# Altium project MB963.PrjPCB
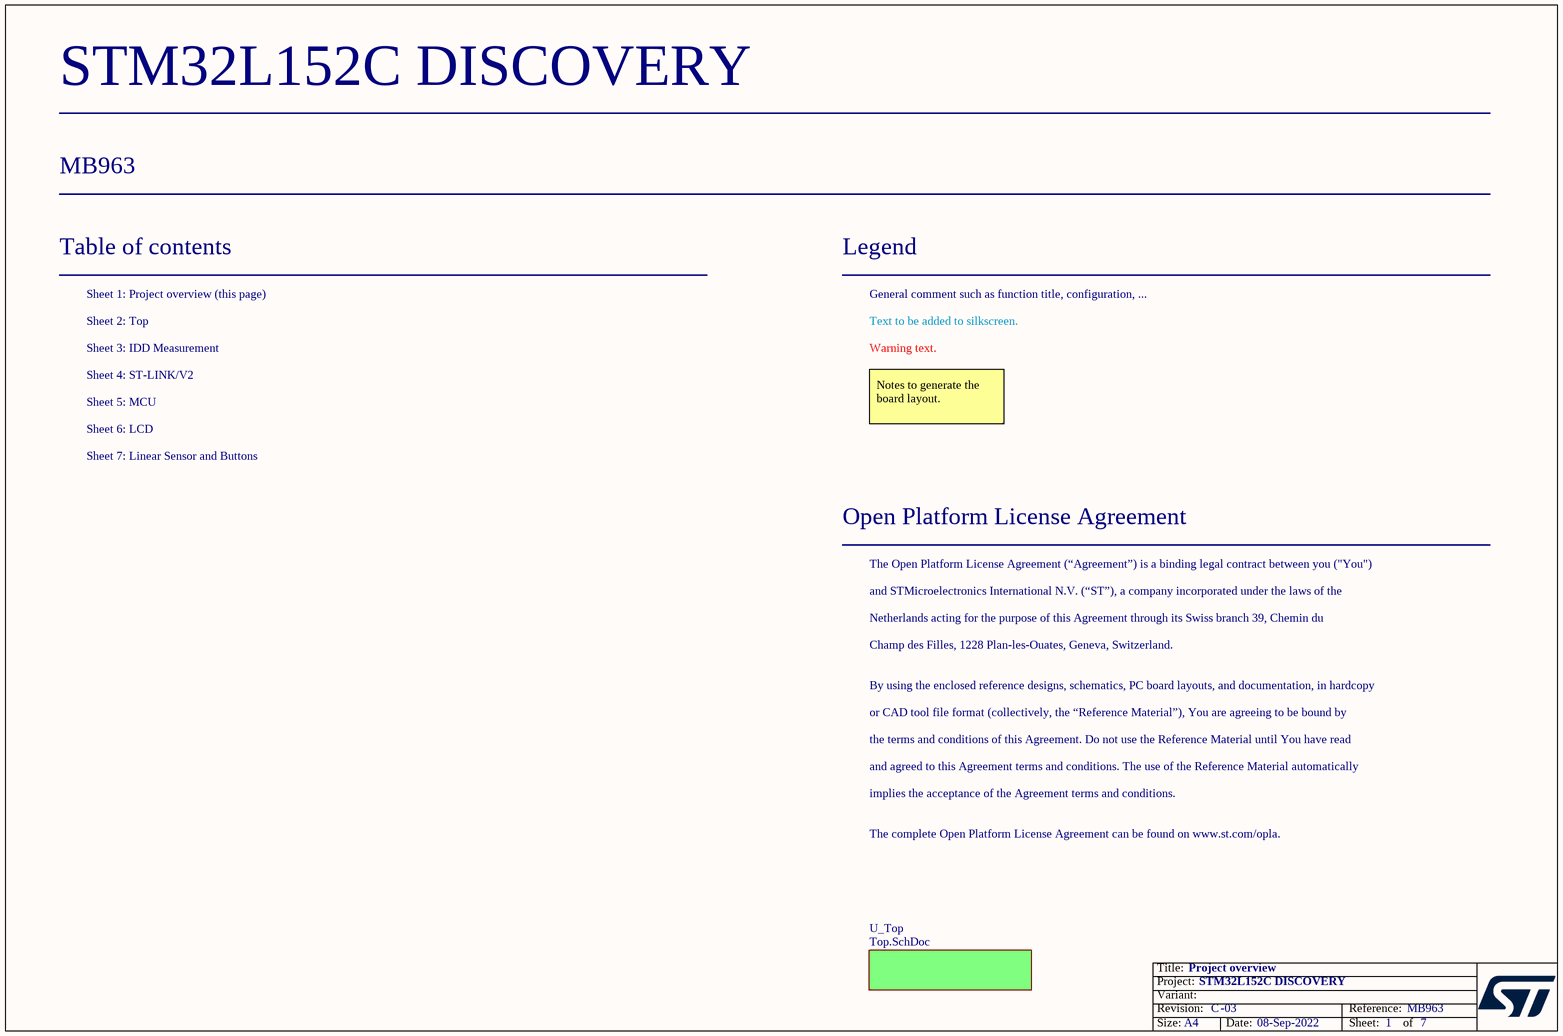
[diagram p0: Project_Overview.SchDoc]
Board_Assembly_Revision: 03; Board_Document_Date: 08-Sep-2022; Board_Name: STM32L152C DISCOVERY; Board_PCB_Revision: C; Board_Reference: MB963
7 sheets, 137 parts. Net scope: flat (ports and power ports of the same name join across sheets).
Board file: mb963b-meca-draw.PCBDOC
Sheets:
  Project_Overview.SchDoc
    U_Top = Top.SchDoc
      U_ST_LINK = ST_LINK.SCHDOC
      U_Power = IDD_measurement.SchDoc
      U_STM32L = STM32L.SchDoc
      U_SLIDER_PB = SLIDER_PB.SchDoc
      U_LCD_GH08172 = LCD_GH08172.SchDoc

## Sheet Project_Overview.SchDoc: Project overview
size A4; Date: Not used; ApprovedBy: Not used; CheckedBy: Not used; Author: Not used; CompanyName: STMicroelectronics; DrawnBy: Not used; Engineer: Not used; Organization: Not used; Address1: Not used; Address2: Not used; Address3: Not used; Address4: Not used; DocumentNumber: Not used; Revision: Not used; SheetNumber: 1; SheetTotal: 7

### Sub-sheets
U_Top = Top.SchDoc: no entries

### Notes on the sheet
- Table of contents
- Sheet 1: Project overview (this page)
- Legend
- General comment such as function title, configuration, ...
- Sheet 2: Top
- Sheet 3: IDD Measurement
- Sheet 4: ST-LINK/V2
- Text to be added to silkscreen.
- Warning text.
- Sheet 5: MCU
- Sheet 6: LCD
- Notes to generate the board layout.
- Sheet 7: Linear Sensor and Buttons
- Open Platform License Agreement
- The Open Platform License Agreement (“Agreement”) is a binding legal contract between you ("You")
- and STMicroelectronics International N.V. (“ST”), a company incorporated under the laws of the
- Netherlands acting for the purpose of this Agreement through its Swiss branch 39, Chemin du
- Champ des Filles, 1228 Plan-les-Ouates, Geneva, Switzerland.
- By using the enclosed reference designs, schematics, PC board layouts, and documentation, in hardcopy
- or CAD tool file format (collectively, the “Reference Material”), You are agreeing to be bound by
- the terms and conditions of this Agreement. Do not use the Reference Material until You have read
- and agreed to this Agreement terms and conditions. The use of the Reference Material automatically
- implies the acceptance of the Agreement terms and conditions.
- The complete Open Platform License Agreement can be found on www.st.com/opla.

## Sheet Top.SchDoc: Top
size A4; PageSetup: Record=PageOptions¦CenterHorizontal=True¦CenterVertical=True¦PrintScale=1.00¦XCorrection=1.00¦YCorrection=1.00¦PrintKind=1¦BorderSize=5000000¦LeftOffset=0¦BottomOffset=0¦Orientation=2¦PaperLength=1000¦PaperWidth=1000¦Scale=100¦PaperSource=15¦PrintQuality=1200¦MediaType=1¦DitherType=10¦PaperKind=A4¦PrintScaleMode=1; Date: Not used; ApprovedBy: Not used; CheckedBy: Not used; Author: Not used; CompanyName: STMicroelectronics; DrawnBy: Not used; Engineer: Not used; Organization: Not used; Address1: Not used; Address2: Not used; Address3: Not used; Address4: Not used; DocumentNumber: Not used; Revision: Not used; SheetNumber: 2; SheetTotal: 7
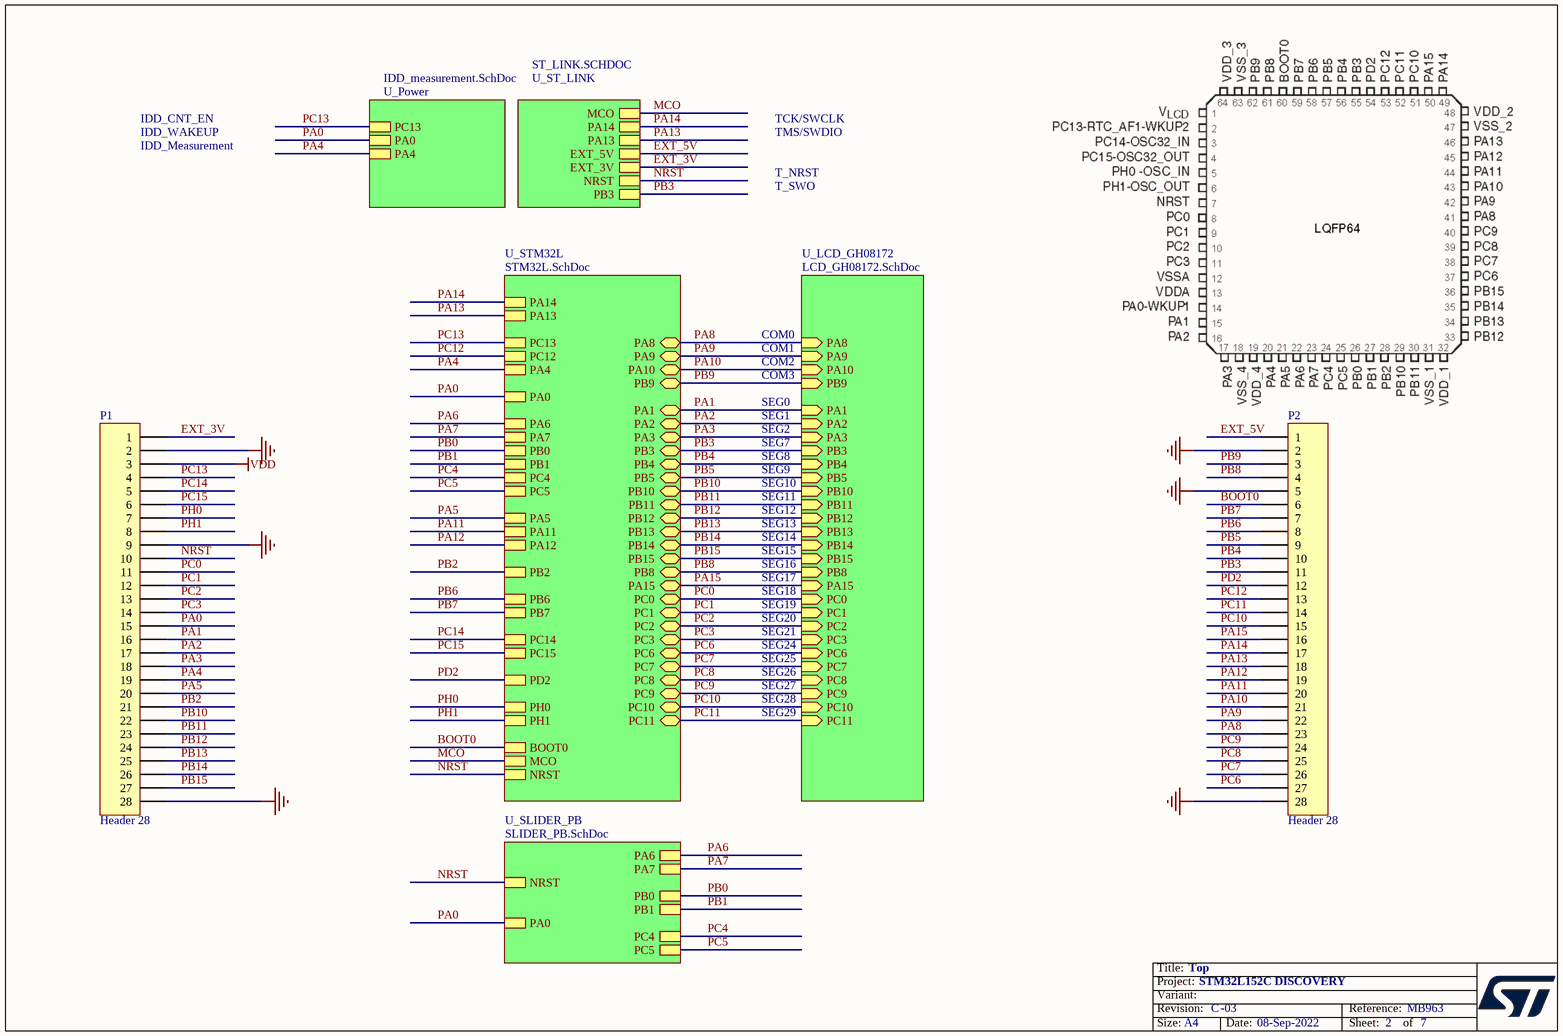
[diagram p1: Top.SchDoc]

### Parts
P1  Header 28  [HDR1X28]
P2  Header 28  [HDR1X28]

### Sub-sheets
U_LCD_GH08172 = LCD_GH08172.SchDoc: PB8 (in), PA15 (in), PB15 (in), PC2 (in), PC1 (in), PC0 (in), PC11 (in), PC10 (in), PC9 (in), PC8 (in), PC3 (in), PC7 (in), PC6 (in), PA8 (in), PA9 (in), PA10 (in), PA1 (in), PA2 (in), PA3 (in), PB3 (in), PB4 (in), PB5 (in), PB10 (in), PB11 (in), PB9 (in), PB12 (in), PB13 (in), PB14 (in)
U_Power = IDD_measurement.SchDoc: PA4, PA0, PC13
U_SLIDER_PB = SLIDER_PB.SchDoc: NRST, PA0, PB0, PC4, PA6, PA7, PC5, PB1
U_ST_LINK = ST_LINK.SCHDOC: PA13, PA14, EXT_5V, EXT_3V, MCO, NRST, PB3
U_STM32L = STM32L.SchDoc: PA13, PA14, PA15 (bidir), PA12, PA0, PA1 (bidir), PA2 (bidir), PA3 (bidir), PA4, PA5, PA6, PA7, PA8 (bidir), PA9 (bidir), PA10 (bidir), PA11, PB12 (bidir), PB0, PB1, PB2, PB3 (bidir), PB4 (bidir), PB5 (bidir), PB6, PB7, PB8 (bidir), PB9 (bidir), PB10 (bidir), PB11 (bidir), PB13 (bidir), PB14 (bidir), PB15 (bidir), PC3 (bidir), PC15, PC14, PC13, PC12, PC11 (bidir), PC10 (bidir), PC9 (bidir), PC8 (bidir), PC7 (bidir), PC6 (bidir), PC5, PC4, PC2 (bidir), PC1 (bidir), PC0 (bidir), PD2, BOOT0, PH1, PH0, NRST, MCO

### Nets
GND: P1.2 P1.9 P1.28 P2.2 P2.5 P2.28
VDD: P1.3
BOOT0: P2.6 ; sheet U_STM32L/BOOT0
EXT_3V: P1.1 ; sheet U_ST_LINK/EXT_3V
EXT_5V: P2.1 ; sheet U_ST_LINK/EXT_5V
MCO: sheet U_ST_LINK/MCO, sheet U_STM32L/MCO
NRST: P1.10 ; sheet U_ST_LINK/NRST, sheet U_STM32L/NRST, sheet U_SLIDER_PB/NRST
PA0: P1.15 ; sheet U_Power/PA0, sheet U_STM32L/PA0, sheet U_SLIDER_PB/PA0
PA1: P1.16 ; sheet U_STM32L/PA1, sheet U_LCD_GH08172/PA1
PA2: P1.17 ; sheet U_STM32L/PA2, sheet U_LCD_GH08172/PA2
PA3: P1.18 ; sheet U_STM32L/PA3, sheet U_LCD_GH08172/PA3
PA4: P1.19 ; sheet U_Power/PA4, sheet U_STM32L/PA4
PA5: P1.20 ; sheet U_STM32L/PA5
PA6: sheet U_STM32L/PA6, sheet U_SLIDER_PB/PA6
PA7: sheet U_STM32L/PA7, sheet U_SLIDER_PB/PA7
PA8: P2.23 ; sheet U_STM32L/PA8, sheet U_LCD_GH08172/PA8
PA9: P2.22 ; sheet U_STM32L/PA9, sheet U_LCD_GH08172/PA9
PA10: P2.21 ; sheet U_STM32L/PA10, sheet U_LCD_GH08172/PA10
PA11: P2.20 ; sheet U_STM32L/PA11
PA12: P2.19 ; sheet U_STM32L/PA12
PA13: P2.18 ; sheet U_ST_LINK/PA13, sheet U_STM32L/PA13
PA14: P2.17 ; sheet U_ST_LINK/PA14, sheet U_STM32L/PA14
PA15: P2.16 ; sheet U_STM32L/PA15, sheet U_LCD_GH08172/PA15
PB0: sheet U_STM32L/PB0, sheet U_SLIDER_PB/PB0
PB1: sheet U_STM32L/PB1, sheet U_SLIDER_PB/PB1
PB2: P1.21 ; sheet U_STM32L/PB2
PB3: P2.11 ; sheet U_ST_LINK/PB3, sheet U_STM32L/PB3, sheet U_LCD_GH08172/PB3
PB4: P2.10 ; sheet U_STM32L/PB4, sheet U_LCD_GH08172/PB4
PB5: P2.9 ; sheet U_STM32L/PB5, sheet U_LCD_GH08172/PB5
PB6: P2.8 ; sheet U_STM32L/PB6
PB7: P2.7 ; sheet U_STM32L/PB7
PB8: P2.4 ; sheet U_STM32L/PB8, sheet U_LCD_GH08172/PB8
PB9: P2.3 ; sheet U_STM32L/PB9, sheet U_LCD_GH08172/PB9
PB10: P1.22 ; sheet U_STM32L/PB10, sheet U_LCD_GH08172/PB10
PB11: P1.23 ; sheet U_STM32L/PB11, sheet U_LCD_GH08172/PB11
PB12: P1.24 ; sheet U_STM32L/PB12, sheet U_LCD_GH08172/PB12
PB13: P1.25 ; sheet U_STM32L/PB13, sheet U_LCD_GH08172/PB13
PB14: P1.26 ; sheet U_STM32L/PB14, sheet U_LCD_GH08172/PB14
PB15: P1.27 ; sheet U_STM32L/PB15, sheet U_LCD_GH08172/PB15
PC0: P1.11 ; sheet U_STM32L/PC0, sheet U_LCD_GH08172/PC0
PC1: P1.12 ; sheet U_STM32L/PC1, sheet U_LCD_GH08172/PC1
PC2: P1.13 ; sheet U_STM32L/PC2, sheet U_LCD_GH08172/PC2
PC3: P1.14 ; sheet U_STM32L/PC3, sheet U_LCD_GH08172/PC3
PC4: sheet U_STM32L/PC4, sheet U_SLIDER_PB/PC4
PC5: sheet U_STM32L/PC5, sheet U_SLIDER_PB/PC5
PC6: P2.27 ; sheet U_STM32L/PC6, sheet U_LCD_GH08172/PC6
PC7: P2.26 ; sheet U_STM32L/PC7, sheet U_LCD_GH08172/PC7
PC8: P2.25 ; sheet U_STM32L/PC8, sheet U_LCD_GH08172/PC8
PC9: P2.24 ; sheet U_STM32L/PC9, sheet U_LCD_GH08172/PC9
PC10: P2.15 ; sheet U_STM32L/PC10, sheet U_LCD_GH08172/PC10
PC11: P2.14 ; sheet U_STM32L/PC11, sheet U_LCD_GH08172/PC11
PC12: P2.13 ; sheet U_STM32L/PC12
PC13: P1.4 ; sheet U_Power/PC13, sheet U_STM32L/PC13
PC14: P1.5 ; sheet U_STM32L/PC14
PC15: P1.6 ; sheet U_STM32L/PC15
PD2: P2.12 ; sheet U_STM32L/PD2
PH0: P1.7 ; sheet U_STM32L/PH0
PH1: P1.8 ; sheet U_STM32L/PH1

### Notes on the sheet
- IDD_WAKEUP
- IDD_CNT_EN
- IDD_Measurement
- TCK/SWCLK
- TMS/SWDIO
- T_NRST
- T_SWO
- COM0
- COM1
- COM2
- COM3
- SEG0
- SEG1
- SEG2
- SEG7
- SEG8
- SEG9
- SEG10
- SEG11
- SEG12
- SEG13
- SEG14
- SEG15
- SEG16
- SEG17
- SEG18
- SEG19
- SEG20
- SEG21
- SEG24
- SEG25
- SEG26
- SEG27
- SEG28
- SEG29

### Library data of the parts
P1 P2 = Header 28: Header, 28-Pin

## Sheet ST_LINK.SCHDOC: ST-LINK/V2 (SWD only)
size A4; Date: Not used; ApprovedBy: Not used; CheckedBy: Not used; Author: Not used; CompanyName: STMicroelectronics; DrawnBy: Not used; Engineer: Not used; Organization: Not used; Address1: Not used; Address2: Not used; Address3: Not used; Address4: Not used; DocumentNumber: Not used; Revision: Not used; SheetNumber: 4; SheetTotal: 7
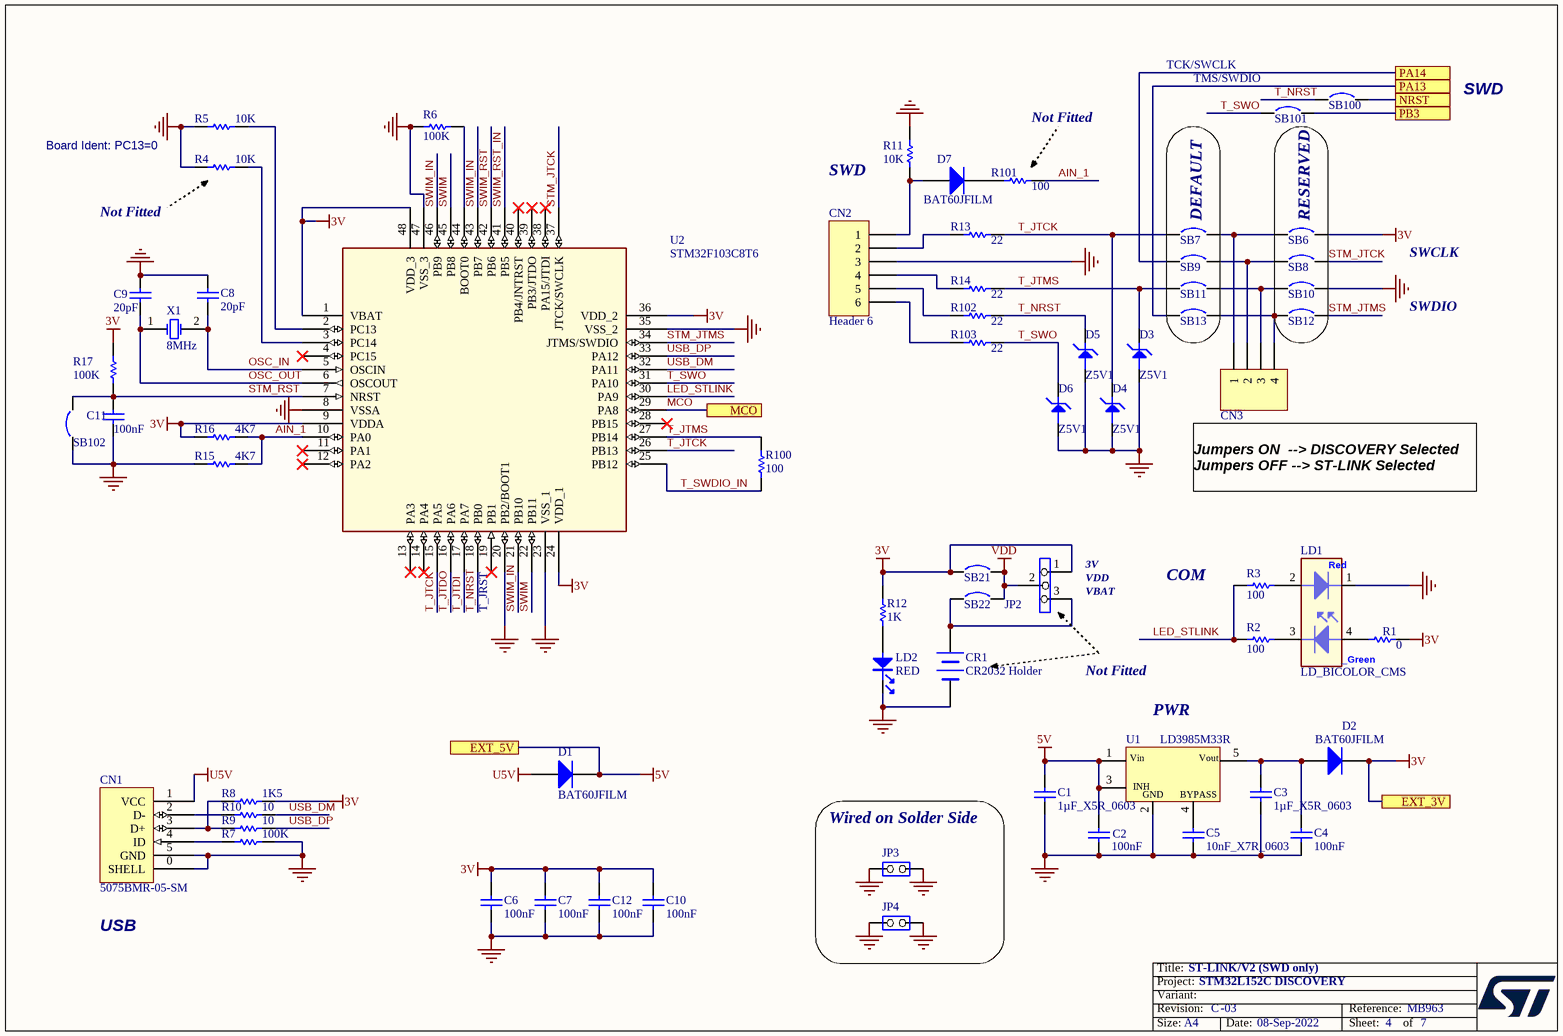
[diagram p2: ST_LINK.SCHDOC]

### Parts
C1  1µF_X5R_0603  [0603C]
C2  100nF  [0603C]
C3  1µF_X5R_0603  [0603C]
C4  100nF  [0603C]
C5  10nF_X7R_0603  [0603C]
C6  100nF  [0402C]
C7  100nF  [0402C]
C8  20pF  [0402C]
C9  20pF  [0402C]
C10  100nF  [0402C]
C11  100nF  [0402C]
C12  100nF  [0402C]
CN1  5075BMR-05-SM  [USB-MINI-B-SMD]
CN2  Header 6  [HDR1X6]
CN3  Header 4  [Header 4]  (value not drawn)
CR1  CR2032 Holder  [SOCKET BATTERY CR2032 (TRAV)]
D1  BAT60JFILM  [SOD323/A]
D2  BAT60JFILM  [SOD323/A]
D3  Z5V1  [SOT-23]
D4  Z5V1  [SOT-23]
D5  Z5V1  [SOT-23]
D6  Z5V1  [SOT-23]
D7  BAT60JFILM  [SOD323/A]
JP2  (no value)  [SIP3]
JP3  (no value)  [SIP2/2.54]
JP4  (no value)  [SIP2/2.54]
LD1  LD_BICOLOR_CMS  [HSMF-A201]
LD2  RED  [0603D]
R1  0  [0402R]
R2  100  [0402R]
R3  100  [0402R]
R4  10K  [0402R]
R5  10K  [0402R]
R6  100K  [0402R]
R7  100K  [0402R]
R8  1K5  [0402R]
R9  10  [0603R]
R10  10  [0603R]
R11  10K  [0402R]
R12  1K  [0402R]
R13  22  [0402R]
R14  22  [0402R]
R15  4K7  [0402R]
R16  4K7  [0402R]
R17  100K  [0402R]
R100  100  [0402R]
R101  100  [0402R]
R102  22  [0402R]
R103  22  [0402R]
SB6  Circuit Breaker  [JP2_SMD]  (value not drawn)
SB7  Circuit Breaker  [JP2_SMD]  (value not drawn)
SB8  Circuit Breaker  [JP2_SMD]  (value not drawn)
SB9  Circuit Breaker  [JP2_SMD]  (value not drawn)
SB10  Circuit Breaker  [JP2_SMD]  (value not drawn)
SB11  Circuit Breaker  [JP2_SMD]  (value not drawn)
SB12  Circuit Breaker  [JP2_SMD]  (value not drawn)
SB13  Circuit Breaker  [JP2_SMD]  (value not drawn)
SB21  Circuit Breaker  [JP2_SMD]  (value not drawn)
SB22  Circuit Breaker  [JP2_SMD]  (value not drawn)
SB100  Circuit Breaker  [JP2_SMD]  (value not drawn)
SB101  Circuit Breaker  [JP2_SMD]  (value not drawn)
SB102  Circuit Breaker  [JP2_SMD]  (value not drawn)
U1  LD3985M33R  [SOT-23-5L]
U2  STM32F103C8T6  [QFP48 7X7]
X1  8MHz  [XTAL1]

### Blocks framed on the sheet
DEFAULT: SB7 SB9 SB11 SB13
RESERVED: SB6 SB8 SB10 SB12
Wired on Solder Side: JP3 JP4

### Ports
EXT_3V, EXT_5V, MCO, NRST, PA13, PA14, PB3

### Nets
3V: C6.2 C7.2 C10.2 C12.1 D2.2(K) JP2.1 R1.2 R8.2 R12.2 R16.1 R17.2 SB6.2 SB21.1 U2.1(VBAT) U2.9(VDDA) U2.24(VDD_1) U2.36(VDD_2) U2.48(VDD_3) ; port EXT_3V
5V: C1.2 C2.2 D1.2(K) U1.1(Vin) U1.3(CE) ; port EXT_5V
GND: C1.1 C2.1 C3.2 C4.1 C5.1 C6.1 C7.1 C8.1 C9.1 C10.1 C11.1 C12.2 CN1.0(SHELL) CN1.5(GND) CN2.3 CR1.2(-) D3.2 D4.2 D5.2 D6.2 JP3.1(COMMON) JP3.2(NO) JP4.1(COMMON) JP4.2(NO) LD1.1 LD2.2 R4.1 R5.1 R6.1 R7.2 R11.2 R15.1 SB10.2 SB102.1 U1.2(GND) U2.8(VSSA) U2.20(PB2/BOOT1) U2.23(VSS_1) U2.35(VSS_2) U2.47(VSS_3)
U5V: CN1.1(VCC) D1.1(A)
VDD: JP2.2 SB21.2 SB22.2
AIN_1: R15.2 R16.2 R101.2 U2.10(PA0)
LED_STLINK: R2.1 R3.1 U2.30(PA9)
MCO: U2.29(PA8) ; port MCO
NRST: SB100.2 ; port NRST
OSC_IN: C8.2 U2.5(OSCIN) X1.2(OSC2)
OSC_OUT: C9.2 U2.6(OSCOUT) X1.1(OSC1)
PA13: SB13.1 ; port PA13
PA14: SB9.1 ; port PA14
PB3: SB101.2 ; port PB3
STM_JTCK: SB8.2 U2.37(JTCK/SWCLK)
STM_JTMS: SB12.2 U2.34(JTMS/SWDIO)
STM_RST: C11.2 R17.1 SB102.2 U2.7(NRST)
SWIM: U2.22(PB11) U2.45(PB8)
SWIM_IN: U2.21(PB10) U2.43(PB7) U2.46(PB9)
SWIM_RST: U2.42(PB6)
SWIM_RST_IN: U2.41(PB5)
T_JTCK: D4.3 R13.2 SB7.1 U2.15(PA5) U2.26(PB13)
T_JTDI: U2.17(PA7)
T_JTDO: U2.16(PA6)
T_JTMS: D3.3 R14.2 R100.2 SB11.1 U2.27(PB14)
T_NRST: D5.3 R102.2 SB100.1 U2.18(PB0)
T_SWDIO_IN: R100.1 U2.25(PB12)
T_SWO: D6.3 R103.2 SB101.1 U2.31(PA10)
USB_DM: R10.2 U2.32(PA11)
USB_DP: R9.2 U2.33(PA12)
NetC3_1: C3.1 C4.2 D2.1(A) U1.5(Vout)
NetC5_2: C5.2 U1.4(BYPASS)
NetCN1_2: CN1.2(D-) R10.1
NetCN1_3: CN1.3(D+) R8.1 R9.1
NetCN1_4: CN1.4(ID) R7.1
NetCN2_1: CN2.1 D7.1(A) R11.1
NetCN2_2: CN2.2 R13.1
NetCN2_4: CN2.4 R14.1
NetCN2_5: CN2.5 R102.1
NetCN2_6: CN2.6 R103.1
NetCN3_1: CN3.1 SB6.1 SB7.2
NetCN3_2: CN3.2 SB8.1 SB9.2
NetCN3_3: CN3.3 SB10.1 SB11.2
NetCN3_4: CN3.4 SB12.1 SB13.2
NetCR1_1: CR1.1(+) JP2.3 SB22.1
NetD7_2: D7.2(K) R101.1
NetLD1_2: LD1.2 R3.2
NetLD1_3: LD1.3 R2.2
NetLD1_4: LD1.4 R1.1
NetLD2_1: LD2.1 R12.1
NetR4_2: R4.2 U2.3(PC14)
NetR5_2: R5.2 U2.2(PC13)
NetR6_2: R6.2 U2.44(BOOT0)

Not connected (* = marked no-connect by the designer): U2 4(PC15)* 11(PA1)* 12(PA2)* 13(PA3)* 14(PA4)* 19(PB1)* 28(PB15)* 38(PA15/JTDI)* 39(PB3/JTDO)* 40(PB4/JNTRST)*

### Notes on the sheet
- TCK/SWCLK
- (near SB101) TMS/SWDIO
- SWD
- Board Ident: PC13=0
- Not Fitted
- SWCLK
- SWDIO
- Jumpers ON  --> DISCOVERY Selected
  Jumpers OFF --> ST-LINK Selected
- (near JP2) 3V
- (near JP2) VDD
- COM
- (near U2) T_JRST
- (near JP2) VBAT
- (near U1) PWR
- USB

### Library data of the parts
C1 C3 = CAP SMD 0603  X5R 1µF 25V 10%: 0603  X5R 1µF; Rated voltage: 25V; Tolerance: 10%
C2 C4 C6-C12 = Cap: Capacitor
C5 = CAP SMD 0603  X7R 10000PF 50V 10%: 0603  X7R 10NF; Order code RS: 2040779; Rated voltage: 50V; Tolerance: 10%
CN1 = USB-MINI-typeB connector
CN2 = Header 6: Header, 6-Pin
CN3 = Header 4: Header, 4-Pin
CR1 = BATTERY: Battery CR2032 with SOCKET; Manuf_1: Lotes; Manuf_Part_1: KB7410AP2L; Fitted: NO
D1 D2 D7 = Diode: Default Diode; Code - JEDEC: DO-214-AB; Provided: ST
D3-D6 = Z5V6: BZX84-C5V6; Fitted: NO
JP2 = Jumper3: Fitted: NO
JP3 JP4 = JP2
LD1 = LD_BICOLOR_CMS: Bicolor Led; Manuf_Part_1: HSMF-A201-A00J1; Manuf_1: Avago Technologies; Ref St: xxxxxx; cap_dec: ----
LD2 = PHOTO
R1-R3 R5-R17 R100 R102 R103 = res1: Resistor
R4 R101 = res1: Resistor; Fitted: NO
SB6 SB8 SB10 SB12 SB21 SB100 SB101 = Circuit Breaker: Solder: YES
SB7 SB9 SB11 SB13 SB22 SB102 = Circuit Breaker: Solder: NO
U1 = LD3985: Manuf_1: STM; Provided: ST
U2 = STM32F103C8T6: Manuf_1: STM; Ref St: 9175981; Provided: ST
X1 = XTAL: Crystal Oscillator

## Sheet IDD_measurement.SchDoc: IDD Measurement
size A4; Date: Not used; ApprovedBy: Not used; CheckedBy: Not used; Author: Not used; CompanyName: STMicroelectronics; DrawnBy: Not used; Engineer: Not used; Organization: Not used; Address1: Not used; Address2: Not used; Address3: Not used; Address4: Not used; DocumentNumber: Not used; Revision: Not used; SheetNumber: 3; SheetTotal: 7
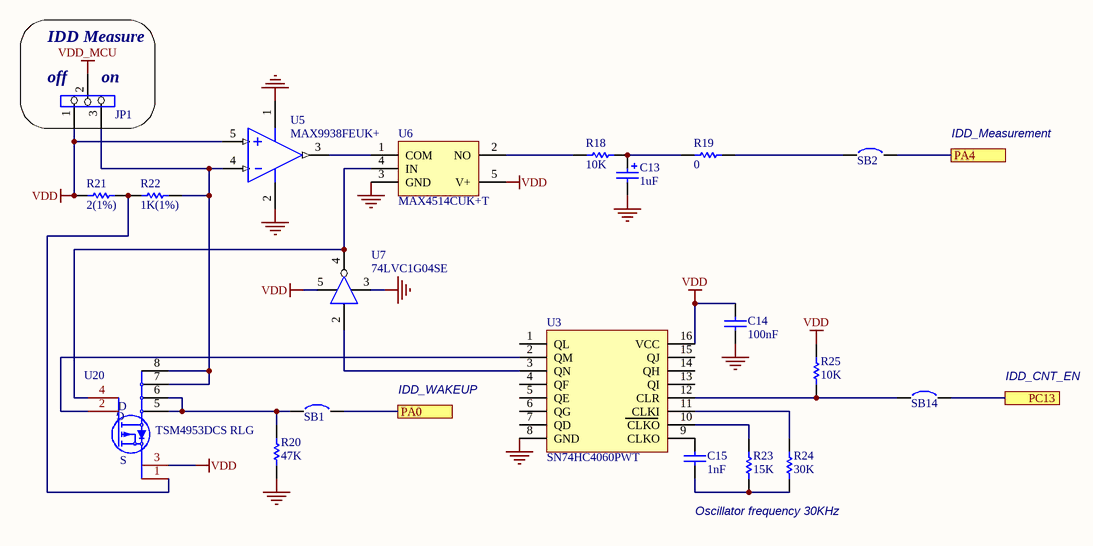
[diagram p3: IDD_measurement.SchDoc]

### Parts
C13  1uF  [0603C]
C14  100nF  [0402C]
C15  1nF  [0402C]
JP1  (no value)  [SIP3]
R18  10K  [0402R]
R19  0  [0402R]
R20  47K  [0402R]
R21  2(1%)  [0402R]
R22  1K(1%)  [0402R]
R23  15K  [0402R]
R24  30K  [0402R]
R25  10K  [0402R]
SB1  Circuit Breaker  [JP2_SMD]  (value not drawn)
SB2  Circuit Breaker  [JP2_SMD]  (value not drawn)
SB14  Circuit Breaker  [JP2_SMD]  (value not drawn)
U3  value SN74HC4060PWT  [ICC_TSSOP16_5P1X4P5_P065]  (hidden comment: SN74HC4060PWx)
U5  MAX9938FEUK+  [SOT-23-5L]
U6  value MAX4514CUK+T  [ICC_SOT23-5L_H1P45]  (hidden comment: MAX4514)
U7  74LVC1G04SE  [DIO_SOT353]
U20  value TSM4953DCS RLG  [ICC_SO8_5X4_P127]  (hidden comment: TSM4953DCS_RLG)

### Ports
PA0, PA4, PC13

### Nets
GND: C13.2 C14.1 R20.2 U3.8(GND) U5.1(GND) U5.2(GND) U6.3(GND) U7.3(GND)
VDD: C14.2 JP1.1 R21.2 R25.1 U3.16(VCC) U5.5(Vp) U6.5(V+) U7.5(VCC) U20.3(S)
VDD_MCU: JP1.2
PA0: SB1.2 ; port PA0
PA4: SB2.2 ; port PA4
PC13: SB14.2 ; port PC13
NetC13_1: C13.1 R18.2 R19.1
NetC15_1: C15.1 U3.9(CLKO)
NetC15_2: C15.2 R23.2 R24.2
NetJP1_3: JP1.3 R22.1 U5.4(Vm) U20.7(D) U20.8(D)
NetR18_1: R18.1 U6.2(NO)
NetR19_2: R19.2 SB2.1
NetR20_1: R20.1 SB1.1 U20.5(D) U20.6(D)
NetR21_1: R21.1 R22.2 U20.1(S)
NetR23_1: R23.1 U3.10(CLKO)
NetR24_1: R24.1 U3.11(CLKI)
NetR25_2: R25.2 SB14.1 U3.12(CLR)
NetU3_2: U3.2(QM) U20.2(S)
NetU3_3: U3.3(QN) U7.2(A)
NetU5_3: U5.3(OUT) U6.1(COM)
NetU6_4: U6.4(IN) U7.4(Y) U20.4(G)

Not connected (* = marked no-connect by the designer): U3 1(QL) 4(QF) 5(QE) 6(QG) 7(QD) 13(QI) 14(QH) 15(QJ); U7 1(NC)

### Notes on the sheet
- (near JP1) IDD Measure
- (near JP1) off
- (near JP1) on
- IDD_Measurement
- IDD_WAKEUP
- IDD_CNT_EN
- Oscillator frequency 30KHz

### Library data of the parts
C13 = Cap Pol1: Polarized Capacitor (Radial)
C14 C15 = Cap: Capacitor
JP1 = Jumper3
R18-R20 R22-R25 = res1: Resistor
R21 = res1: Resistor; Value: 2
SB1 SB2 SB14 = Circuit Breaker: Solder: YES
U3 = MCD-02070: 14-stage asynchronous  binary counter/oscillator; Part_Type: IC; Part_Preference: Recommended; Manufacturer: TEXAS INSTRUMENTS; Component_Country_Of_Origin: Malaysia; ShowFields: YES; ID: 4170
U5 = MAX9938: Precision Current-Sense Amplifier
U6 = MCD-02073: CMOS Analog Switches, Low-Voltage, Low-On-Resistance; Part_Type: IC; Part_Preference: Recommended; Manufacturer: MAXIM INTEGRATED; Order_Code_RS: 191-3316; Component_Country_Of_Origin: Thailand, Malaysia; ShowFields: YES; ID: 4173
U7 = MCD-00126: single Inverter Gate with a standard push-pull output. (1.65V to 5.5V); Part_Type: IC; Part_Preference: Recommended; Manufacturer: DIODES INCORPORATED; Component_Country_Of_Origin: Unknown; ShowFields: YES; ID: 2738
U20 = MCD-03226: Transistor, MOSFET, Dual P-Ch, 30V, -4.9A, SOP-8; Part_Preference: Recommended; Manufacturer: TAIWAN SEMICONDUCTOR; ShowFields: YES; ID: 5342

## Sheet STM32L.SchDoc: MCU
size A4; Date: Not used; ApprovedBy: Not used; CheckedBy: Not used; Author: Not used; CompanyName: STMicroelectronics; DrawnBy: Not used; Engineer: Not used; Organization: Not used; Address1: Not used; Address2: Not used; Address3: Not used; Address4: Not used; DocumentNumber: Not used; Revision: Not used; SheetNumber: 5; SheetTotal: 7
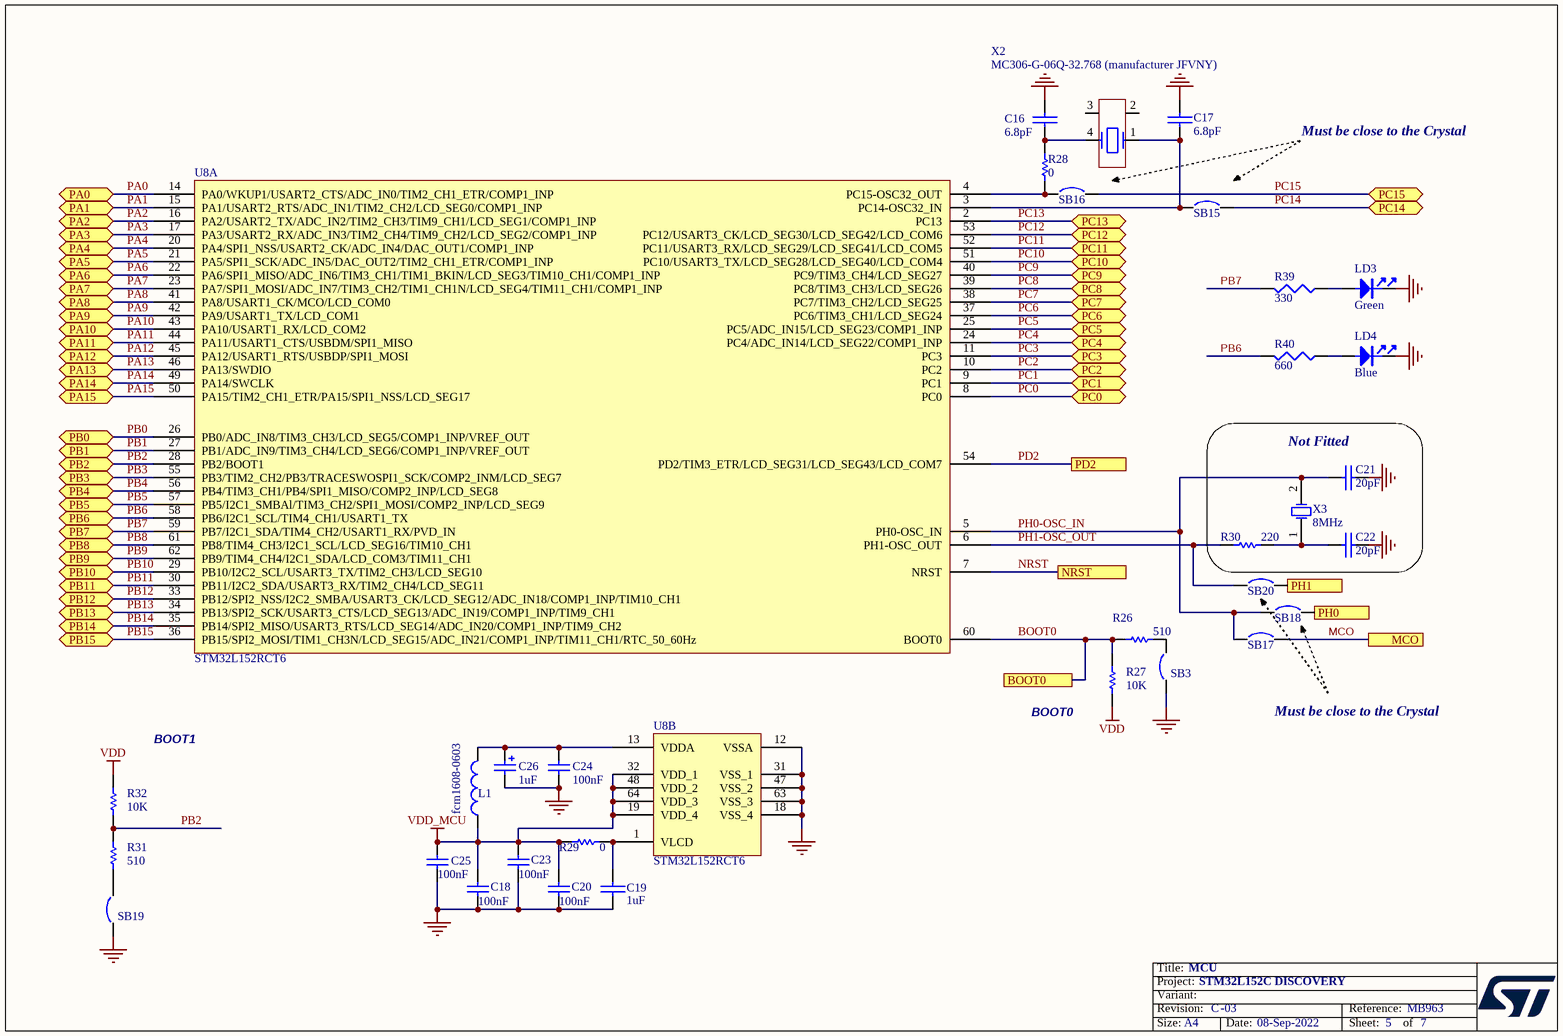
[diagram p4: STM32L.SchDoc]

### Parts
C16  6.8pF  [0603C]
C17  6.8pF  [0603C]
C18  100nF  [0402C]
C19  1uF  [0603C]
C20  100nF  [0402C]
C21  20pF  [0603C]
C22  20pF  [0603C]
C23  100nF  [0402C]
C24  100nF  [0402C]
C25  100nF  [0402C]
C26  1uF  [CASE-AA]
L1  fcm1608-0603  [0603L]
LD3  Green  [0603D]
LD4  Blue  [0603D]
R26  510  [0603R]
R27  10K  [0402R]
R28  0  [0603R]
R29  0  [0402R]
R30  220  [0603R]
R31  510  [0603R]
R32  10K  [0402R]
R39  330  [0603R]
R40  660  [0603R]
SB3  Circuit Breaker  [JP2_SMD]  (value not drawn)
SB15  Circuit Breaker  [JP2_SMD]  (value not drawn)
SB16  Circuit Breaker  [JP2_SMD]  (value not drawn)
SB17  Circuit Breaker  [JP2_SMD]  (value not drawn)
SB18  Circuit Breaker  [JP2_SMD]  (value not drawn)
SB19  Circuit Breaker  [JP2_SMD]  (value not drawn)
SB20  Circuit Breaker  [JP2_SMD]  (value not drawn)
U8  STM32L152RCT6  [QFP64]  (parts A,B of 2)
X2  MC306-G-06Q-32.768 (manufacturer JFVNY)  [MC306-CRYSTAL]
X3  8MHz  [XTAL1]

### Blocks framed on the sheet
Not Fitted: C21 C22 R30 X3

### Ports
BOOT0, MCO, NRST, PA0 (bidir), PA1 (bidir), PA2 (bidir), PA3 (bidir), PA4 (bidir), PA5 (bidir), PA6 (bidir), PA7 (bidir), PA8 (bidir), PA9 (bidir), PA10 (bidir), PA11 (bidir), PA12 (bidir), PA13 (bidir), PA14 (bidir), PA15 (bidir), PB0 (bidir), PB1 (bidir), PB2 (bidir), PB3 (bidir), PB4 (bidir), PB5 (bidir), PB6 (bidir), PB7 (bidir), PB8 (bidir), PB9 (bidir), PB10 (bidir), PB11 (bidir), PB12 (bidir), PB13 (bidir), PB14 (bidir), PB15 (bidir), PC0 (bidir), PC1 (bidir), PC2 (bidir), PC3 (bidir), PC4 (bidir), PC5 (bidir), PC6 (bidir), PC7 (bidir), PC8 (bidir), PC9 (bidir), PC10 (bidir), PC11 (bidir), PC12 (bidir), PC13 (bidir), PC14 (bidir), PC15 (bidir), PD2, PH0, PH1

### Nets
GND: C16.2 C17.2 C18.1 C19.2 C20.1 C21.1 C22.1 C23.2 C24.1 C25.1 C26.2 LD3.2 LD4.2 SB3.1 SB19.1 U8.12(VSSA) U8.18(VSS_4) U8.31(VSS_1) U8.47(VSS_2) U8.63(VSS_3)
VDD: R27.2 R32.1
VDD_MCU: C18.2 C20.2 C23.1 C25.2 L1.1 R29.1 U8.19(VDD_4) U8.32(VDD_1) U8.48(VDD_2) U8.64(VDD_3)
BOOT0: R26.2 R27.1 U8.60(BOOT0) ; port BOOT0
MCO: SB17.2 ; port MCO
NRST: U8.7(NRST) ; port NRST
PA0: U8.14(PA0/WKUP1/USART2_CTS/ADC_IN0/TIM2_CH1_ETR/COMP1_INP) ; port PA0
PA1: U8.15(PA1/USART2_RTS/ADC_IN1/TIM2_CH2/LCD_SEG0/COMP1_INP) ; port PA1
PA2: U8.16(PA2/USART2_TX/ADC_IN2/TIM2_CH3/TIM9_CH1/LCD_SEG1/COMP1_INP) ; port PA2
PA3: U8.17(PA3/USART2_RX/ADC_IN3/TIM2_CH4/TIM9_CH2/LCD_SEG2/COMP1_INP) ; port PA3
PA4: U8.20(PA4/SPI1_NSS/USART2_CK/ADC_IN4/DAC_OUT1/COMP1_INP) ; port PA4
PA5: U8.21(PA5/SPI1_SCK/ADC_IN5/DAC_OUT2/TIM2_CH1_ETR/COMP1_INP) ; port PA5
PA6: U8.22(PA6/SPI1_MISO/ADC_IN6/TIM3_CH1/TIM1_BKIN/LCD_SEG3/TIM10_CH1/COMP1_INP) ; port PA6
PA7: U8.23(PA7/SPI1_MOSI/ADC_IN7/TIM3_CH2/TIM1_CH1N/LCD_SEG4/TIM11_CH1/COMP1_INP) ; port PA7
PA8: U8.41(PA8/USART1_CK/MCO/LCD_COM0) ; port PA8
PA9: U8.42(PA9/USART1_TX/LCD_COM1) ; port PA9
PA10: U8.43(PA10/USART1_RX/LCD_COM2) ; port PA10
PA11: U8.44(PA11/USART1_CTS/USBDM/SPI1_MISO) ; port PA11
PA12: U8.45(PA12/USART1_RTS/USBDP/SPI1_MOSI) ; port PA12
PA13: U8.46(PA13/SWDIO) ; port PA13
PA14: U8.49(PA14/SWCLK) ; port PA14
PA15: U8.50(PA15/TIM2_CH1_ETR/PA15/SPI1_NSS/LCD_SEG17) ; port PA15
PB0: U8.26(PB0/ADC_IN8/TIM3_CH3/LCD_SEG5/COMP1_INP/VREF_OUT) ; port PB0
PB1: U8.27(PB1/ADC_IN9/TIM3_CH4/LCD_SEG6/COMP1_INP/VREF_OUT) ; port PB1
PB2: R31.1 R32.2 U8.28(PB2/BOOT1) ; port PB2
PB3: U8.55(PB3/TIM2_CH2/PB3/TRACESWOSPI1_SCK/COMP2_INM/LCD_SEG7) ; port PB3
PB4: U8.56(PB4/TIM3_CH1/PB4/SPI1_MISO/COMP2_INP/LCD_SEG8) ; port PB4
PB5: U8.57(PB5/I2C1_SMBAl/TIM3_CH2/SPI1_MOSI/COMP2_INP/LCD_SEG9) ; port PB5
PB6: R40.2 U8.58(PB6/I2C1_SCL/TIM4_CH1/USART1_TX) ; port PB6
PB7: R39.2 U8.59(PB7/I2C1_SDA/TIM4_CH2/USART1_RX/PVD_IN) ; port PB7
PB8: U8.61(PB8/TIM4_CH3/I2C1_SCL/LCD_SEG16/TIM10_CH1) ; port PB8
PB9: U8.62(PB9/TIM4_CH4/I2C1_SDA/LCD_COM3/TIM11_CH1) ; port PB9
PB10: U8.29(PB10/I2C2_SCL/USART3_TX/TIM2_CH3/LCD_SEG10) ; port PB10
PB11: U8.30(PB11/I2C2_SDA/USART3_RX/TIM2_CH4/LCD_SEG11) ; port PB11
PB12: U8.33(PB12/SPI2_NSS/I2C2_SMBA/USART3_CK/LCD_SEG12/ADC_IN18/COMP1_INP/TIM10_CH1) ; port PB12
PB13: U8.34(PB13/SPI2_SCK/USART3_CTS/LCD_SEG13/ADC_IN19/COMP1_INP/TIM9_CH1) ; port PB13
PB14: U8.35(PB14/SPI2_MISO/USART3_RTS/LCD_SEG14/ADC_IN20/COMP1_INP/TIM9_CH2) ; port PB14
PB15: U8.36(PB15/SPI2_MOSI/TIM1_CH3N/LCD_SEG15/ADC_IN21/COMP1_INP/TIM11_CH1/RTC_50_60Hz) ; port PB15
PC0: U8.8(PC0) ; port PC0
PC1: U8.9(PC1) ; port PC1
PC2: U8.10(PC2) ; port PC2
PC3: U8.11(PC3) ; port PC3
PC4: U8.24(PC4/ADC_IN14/LCD_SEG22/COMP1_INP) ; port PC4
PC5: U8.25(PC5/ADC_IN15/LCD_SEG23/COMP1_INP) ; port PC5
PC6: U8.37(PC6/TIM3_CH1/LCD_SEG24) ; port PC6
PC7: U8.38(PC7/TIM3_CH2/LCD_SEG25) ; port PC7
PC8: U8.39(PC8/TIM3_CH3/LCD_SEG26) ; port PC8
PC9: U8.40(PC9/TIM3_CH4/LCD_SEG27) ; port PC9
PC10: U8.51(PC10/USART3_TX/LCD_SEG28/LCD_SEG40/LCD_COM4) ; port PC10
PC11: U8.52(PC11/USART3_RX/LCD_SEG29/LCD_SEG41/LCD_COM5) ; port PC11
PC12: U8.53(PC12/USART3_CK/LCD_SEG30/LCD_SEG42/LCD_COM6) ; port PC12
PC13: U8.2(PC13) ; port PC13
PC14: SB15.2 ; port PC14
PC15: SB16.2 ; port PC15
PD2: U8.54(PD2/TIM3_ETR/LCD_SEG31/LCD_SEG43/LCD_COM7) ; port PD2
PH0-OSC_IN: C21.2 SB17.1 SB18.1 U8.5(PH0-OSC_IN) X3.2(OSC2)
PH1-OSC_OUT: R30.2 SB20.1 U8.6(PH1-OSC_OUT)
NetC16_1: C16.1 R28.1 X2.4
NetC17_1: C17.1 SB15.1 U8.3(PC14-OSC32_IN) X2.1
NetC19_1: C19.1 R29.2 U8.1(VLCD)
NetC22_2: C22.2 R30.1 X3.1(OSC1)
NetC24_2: C24.2 C26.1 L1.2 U8.13(VDDA)
NetLD3_1: LD3.1 R39.1
NetLD4_1: LD4.1 R40.1
NetR26_1: R26.1 SB3.2
NetR28_2: R28.2 SB16.1 U8.4(PC15-OSC32_OUT)
NetR31_2: R31.2 SB19.2
NetSB18_2: SB18.2 ; port PH0
NetSB20_2: SB20.2 ; port PH1

Not connected (* = marked no-connect by the designer): X2 2 3

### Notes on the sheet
- Must be close to the Crystal
- (near R27) BOOT0
- BOOT1

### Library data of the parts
C16 C17 C19 = CAP: Capacitor
C18 C20 C23-C25 = Cap: Capacitor
C21 C22 = CAP: Capacitor; Fitted: NO
C26 = Cap Pol1: Polarized Capacitor (Radial); Value: 10uF
L1 = Inductor: Value: 100uH
LD3 LD4 = PHOTO
R26 R28 = Res1: Resistor
R27 R31 R32 = res1: Resistor
R29 = res1: Resistor; Fitted: NO
R30 = Res1: Resistor; Fitted: NO
R39 R40 = RES1
SB3 SB20 = Circuit Breaker: Solder: YES
SB15-SB19 = Circuit Breaker: Solder: NO
U8 = STM32L152RCT6: 32-bit 256K MCU (SCORPIO2 Shrink); Manufaturer_1: STM; Provided: ST; X3 code: 9175126; ECCN US: 3A991A2; ECCN EU: NEC
X2 = MC306
X3 = XTAL: Crystal Oscillator; Fitted: NO

## Sheet SLIDER_PB.SchDoc: Linear Sensor and Buttons
size A4; Date: Not used; ApprovedBy: Not used; CheckedBy: Not used; Author: Not used; CompanyName: STMicroelectronics; DrawnBy: Not used; Engineer: Not used; Organization: Not used; Address1: Not used; Address2: Not used; Address3: Not used; Address4: Not used; DocumentNumber: Not used; Revision: Not used; SheetNumber: 7; SheetTotal: 7
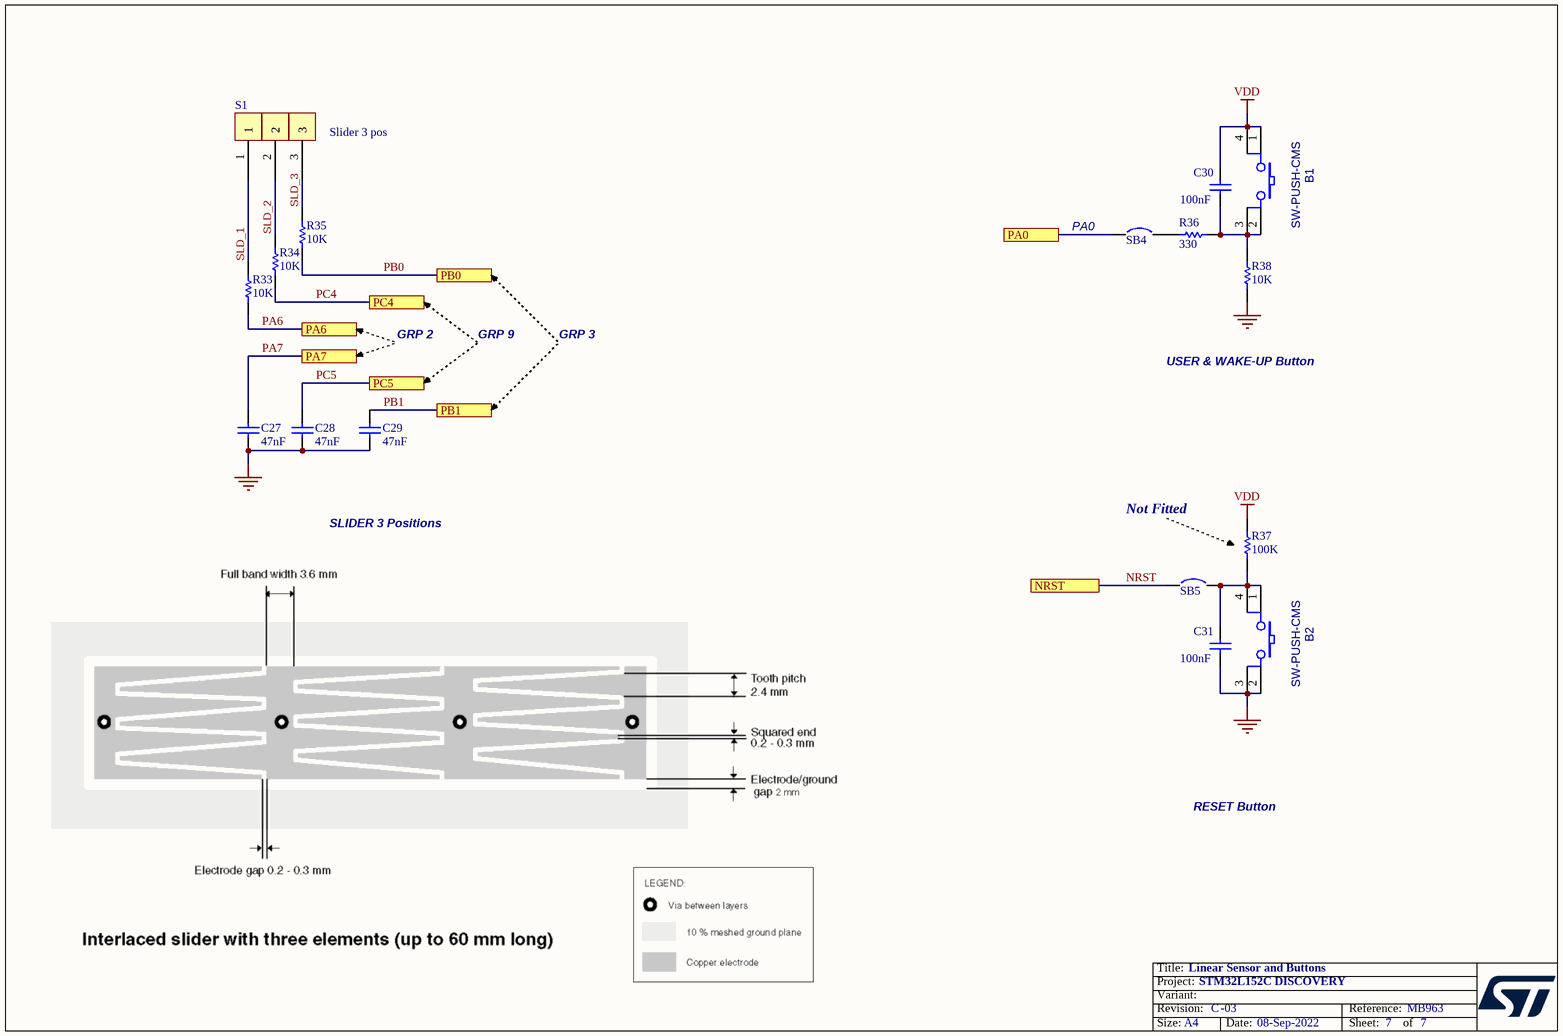
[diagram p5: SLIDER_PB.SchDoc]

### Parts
B1  SW-PUSH-CMS  [BP1CMS]
B2  SW-PUSH-CMS  [BP1CMS]
C27  47nF  [0805C]
C28  47nF  [0805C]
C29  47nF  [0805C]
C30  100nF  [0603C]
C31  100nF  [0603C]
R33  10K  [0402R]
R34  10K  [0402R]
R35  10K  [0402R]
R36  330  [0402R]
R37  100K  [0402R]
R38  10K  [0402R]
S1  Slider 3 pos  [Slider 3-2]
SB4  Circuit Breaker  [JP2_SMD]  (value not drawn)
SB5  Circuit Breaker  [JP2_SMD]  (value not drawn)

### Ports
NRST, PA0, PA6, PA7, PB0, PB1, PC4, PC5

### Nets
GND: B2.2 B2.3 C27.1 C28.1 C29.1 C31.1 R38.1
VDD: B1.1 B1.4 C30.2 R37.2
NRST: SB5.1 ; port NRST
PA0: SB4.1 ; port PA0
PA6: R33.1 ; port PA6
PA7: C27.2 ; port PA7
PB0: R35.1 ; port PB0
PB1: C29.2 ; port PB1
PC4: R34.1 ; port PC4
PC5: C28.2 ; port PC5
SLD_1: R33.2 S1.1
SLD_2: R34.2 S1.2
SLD_3: R35.2 S1.3
NetB1_2: B1.2 B1.3 C30.1 R36.2 R38.2
NetB2_1: B2.1 B2.4 C31.2 R37.1 SB5.2
NetR36_1: R36.1 SB4.2

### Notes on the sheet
- (near SB4) PA0
- GRP 2
- GRP 9
- GRP 3
- USER & WAKE-UP Button
- Not Fitted
- SLIDER 3 Positions
- RESET Button

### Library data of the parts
B1 B2 = SW-PUSH-CMS: Non-Open Push-Button 0.1A 24V; Manuf_1: FARNELL; Manuf_Part_1: 535-930; Ref St: 9180120; cap_dec: ---
C27-C29 = CAP: Capacitor; Manuf_1: KEMET; Manuf_Part_1: C0805C473F8GAC
C30 C31 = CAP: Capacitor
R33-R36 R38 = res1: Resistor
R37 = res1: Resistor; Fitted: NO
S1 = Slider 3 pos: plan de cuivre recouvert de vernis + Couche Plastic
SB4 SB5 = Circuit Breaker: Solder: YES

## Sheet LCD_GH08172.SchDoc: LCD
size A4; Date: Not used; ApprovedBy: Not used; CheckedBy: Not used; Author: Not used; CompanyName: STMicroelectronics; DrawnBy: Not used; Engineer: Not used; Organization: Not used; Address1: Not used; Address2: Not used; Address3: Not used; Address4: Not used; DocumentNumber: Not used; Revision: Not used; SheetNumber: 6; SheetTotal: 7
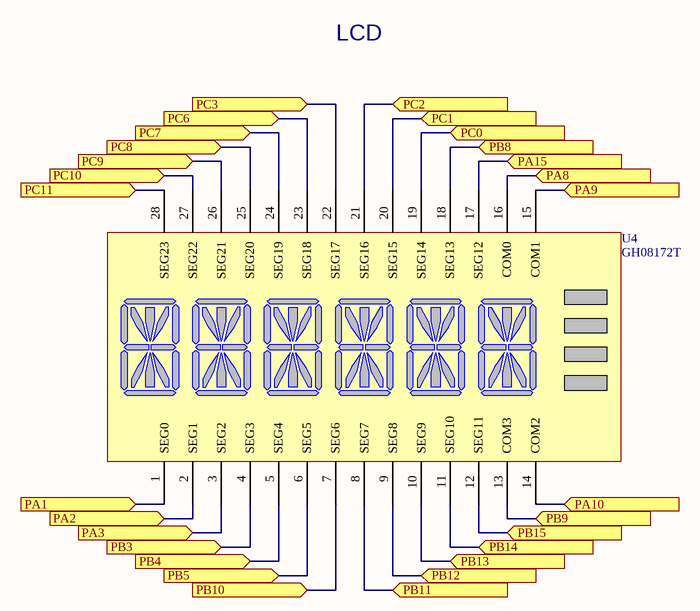
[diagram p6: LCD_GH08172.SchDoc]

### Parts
U4  GH08172T  [DIP28]

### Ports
PA1 (in), PA2 (in), PA3 (in), PA8 (in), PA9 (in), PA10 (in), PA15 (in), PB3 (in), PB4 (in), PB5 (in), PB8 (in), PB9 (in), PB10 (in), PB11 (in), PB12 (in), PB13 (in), PB14 (in), PB15 (in), PC0 (in), PC1 (in), PC2 (in), PC3 (in), PC6 (in), PC7 (in), PC8 (in), PC9 (in), PC10 (in), PC11 (in)

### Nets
PA1: U4.1(SEG0) ; port PA1
PA2: U4.2(SEG1) ; port PA2
PA3: U4.3(SEG2) ; port PA3
PA8: U4.16(COM0) ; port PA8
PA9: U4.15(COM1) ; port PA9
PA10: U4.14(COM2) ; port PA10
PA15: U4.17(SEG12) ; port PA15
PB3: U4.4(SEG3) ; port PB3
PB4: U4.5(SEG4) ; port PB4
PB5: U4.6(SEG5) ; port PB5
PB8: U4.18(SEG13) ; port PB8
PB9: U4.13(COM3) ; port PB9
PB10: U4.7(SEG6) ; port PB10
PB11: U4.8(SEG7) ; port PB11
PB12: U4.9(SEG8) ; port PB12
PB13: U4.10(SEG9) ; port PB13
PB14: U4.11(SEG10) ; port PB14
PB15: U4.12(SEG11) ; port PB15
PC0: U4.19(SEG14) ; port PC0
PC1: U4.20(SEG15) ; port PC1
PC2: U4.21(SEG16) ; port PC2
PC3: U4.22(SEG17) ; port PC3
PC6: U4.23(SEG18) ; port PC6
PC7: U4.24(SEG19) ; port PC7
PC8: U4.25(SEG20) ; port PC8
PC9: U4.26(SEG21) ; port PC9
PC10: U4.27(SEG22) ; port PC10
PC11: U4.28(SEG23) ; port PC11

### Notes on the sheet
- LCD

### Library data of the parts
U4 = GH08172T: LCD 24 Seg x 4 Com with SOCKET

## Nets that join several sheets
GND: Top (6 pins), ST_LINK (40 pins), IDD_measurement (8 pins), STM32L (20 pins), SLIDER_PB (7 pins)
VDD: Top (P1.3), ST_LINK (JP2.2 SB21.2 SB22.2), IDD_measurement (9 pins), STM32L (R27.2 R32.1), SLIDER_PB (B1.1 B1.4 C30.2 R37.2)
VDD_MCU: IDD_measurement (JP1.2), STM32L (10 pins)
MCO: ST_LINK (U2.29), STM32L (SB17.2)
NRST: ST_LINK (SB100.2), STM32L (U8.7), SLIDER_PB (SB5.1)
PA0: IDD_measurement (SB1.2), STM32L (U8.14), SLIDER_PB (SB4.1)
PA1: STM32L (U8.15), LCD_GH08172 (U4.1)
PA2: STM32L (U8.16), LCD_GH08172 (U4.2)
PA3: STM32L (U8.17), LCD_GH08172 (U4.3)
PA4: IDD_measurement (SB2.2), STM32L (U8.20)
PA6: STM32L (U8.22), SLIDER_PB (R33.1)
PA7: STM32L (U8.23), SLIDER_PB (C27.2)
PA8: STM32L (U8.41), LCD_GH08172 (U4.16)
PA9: STM32L (U8.42), LCD_GH08172 (U4.15)
PA10: STM32L (U8.43), LCD_GH08172 (U4.14)
PA13: ST_LINK (SB13.1), STM32L (U8.46)
PA14: ST_LINK (SB9.1), STM32L (U8.49)
PA15: STM32L (U8.50), LCD_GH08172 (U4.17)
PB0: STM32L (U8.26), SLIDER_PB (R35.1)
PB1: STM32L (U8.27), SLIDER_PB (C29.2)
PB3: ST_LINK (SB101.2), STM32L (U8.55), LCD_GH08172 (U4.4)
PB4: STM32L (U8.56), LCD_GH08172 (U4.5)
PB5: STM32L (U8.57), LCD_GH08172 (U4.6)
PB8: STM32L (U8.61), LCD_GH08172 (U4.18)
PB9: STM32L (U8.62), LCD_GH08172 (U4.13)
PB10: STM32L (U8.29), LCD_GH08172 (U4.7)
PB11: STM32L (U8.30), LCD_GH08172 (U4.8)
PB12: STM32L (U8.33), LCD_GH08172 (U4.9)
PB13: STM32L (U8.34), LCD_GH08172 (U4.10)
PB14: STM32L (U8.35), LCD_GH08172 (U4.11)
PB15: STM32L (U8.36), LCD_GH08172 (U4.12)
PC0: STM32L (U8.8), LCD_GH08172 (U4.19)
PC1: STM32L (U8.9), LCD_GH08172 (U4.20)
PC2: STM32L (U8.10), LCD_GH08172 (U4.21)
PC3: STM32L (U8.11), LCD_GH08172 (U4.22)
PC4: STM32L (U8.24), SLIDER_PB (R34.1)
PC5: STM32L (U8.25), SLIDER_PB (C28.2)
PC6: STM32L (U8.37), LCD_GH08172 (U4.23)
PC7: STM32L (U8.38), LCD_GH08172 (U4.24)
PC8: STM32L (U8.39), LCD_GH08172 (U4.25)
PC9: STM32L (U8.40), LCD_GH08172 (U4.26)
PC10: STM32L (U8.51), LCD_GH08172 (U4.27)
PC11: STM32L (U8.52), LCD_GH08172 (U4.28)
PC13: IDD_measurement (SB14.2), STM32L (U8.2)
